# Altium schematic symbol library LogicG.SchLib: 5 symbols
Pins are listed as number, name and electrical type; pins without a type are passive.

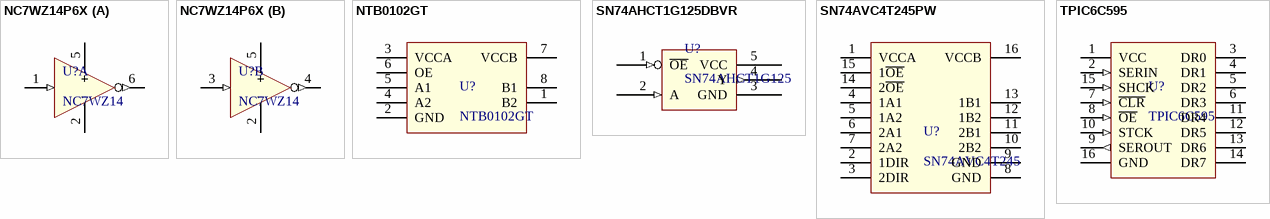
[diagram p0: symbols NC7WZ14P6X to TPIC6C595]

## NC7WZ14P6X
designator U?, comment NC7WZ14
Dual Inverter with Schmitt Trigger
footprint SC70-LT6_N (Footprint not found)
part A pins: 1 A1 (in), 2 GND (power), 5 VCC (power), 6 Y1 (out)
part B pins: 2 GND (power), 3 A2 (in), 4 Y2 (out), 5 VCC (power)

## NTB0102GT
designator U?
2-bit auto-sensing transceiver
pins: 1 B2, 2 GND, 3 VCCA, 4 A2, 5 A1, 6 OE, 7 VCCB, 8 B1

## SN74AHCT1G125DBVR
designator U?, comment SN74AHCT1G125
Single bus buffer gate with 3-state output
footprint DBV005 (SOT-23/SC-74A; 5 Leads; Body 3 x 3 mm, inc. leads (LxW max))
pins: 1 ~{OE} (in), 2 A (in), 3 GND (power), 4 Y (out), 5 VCC (power)

## SN74AVC4T245PW
designator U?, comment SN74AVC4T245
4-bit Bus Transceiver
footprint PW016 (Shrink Small Outline; 16 Leads; Body Width 4.4 mm; Pitch 0.65 mm)
footprint D016_N (16-Pin Small Outline Integrated Circuit 1.27 mm Pitch, IPC Medium Density)
pins: 1 VCCA, 2 1DIR, 3 2DIR, 4 1A1, 5 1A2, 6 2A1, 7 2A2, 8 GND, 9 GND, 10 2B2, 11 2B1, 12 1B2, 13 1B1, 14 2~{OE}, 15 1~{OE}, 16 VCCB

## TPIC6C595
designator U?
footprint PW016 (Shrink Small Outline; 16 Leads; Body Width 4.4 mm; Pitch 0.65 mm)
pins: 1 VCC (power), 2 SERIN (in), 3 DR0 (oc), 4 DR1 (oc), 5 DR2 (oc), 6 DR3 (oc), 7 ~{CLR} (in), 8 ~{OE} (in), 9 SEROUT (out), 10 STCK (in), 11 DR4 (oc), 12 DR5 (oc), 13 DR6 (oc), 14 DR7 (oc), 15 SHCK (in), 16 GND (power)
